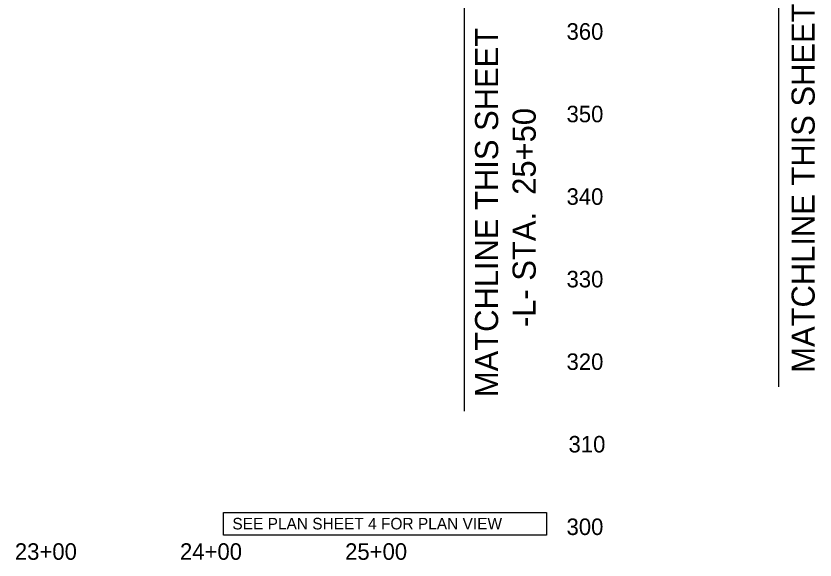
# Model space of a CAD drawing. Extents: x 2044664 to 2046614, y 755540 to 756566.
# Drawn here: x 2046130.2 to 2046614.2, y 756065.3 to 756394.8 of the extents above; entities that cross this region are included whole.
import ezdxf

# ---------------------------------------------------------------- set-up
doc = ezdxf.new("R2010")
doc.units = 0
for name, color, linetype in [('Exist Vertical Profile Horizontal Axis Label Major', 7, 'Continuous'), ('Exist Vertical Profile Vertical Axis Label', 7, 'Continuous'), ('Matchline', 7, 'Continuous'), ('Matchline Text', 7, 'Continuous'), ('Prop Grid Mask', 7, 'Continuous')]:
    doc.layers.add(name, color=color, linetype=linetype)

msp = doc.modelspace()

# ---------------------------------------------------------------- linework, layer by layer
at = {"layer": 'Matchline'}
for p, q in [((2046591.97, 756434.13), (2046591.97, 756170.18)), ((2046401.63, 756419.36), (2046401.63, 756155.41))]:
    msp.add_line(p, q, dxfattribs=at)
at = {"layer": 'Prop Grid Mask'}
msp.add_lwpolyline([(2046451.63, 756080.41), (2046255.85, 756080.42), (2046255.85, 756094.07), (2046451.64, 756094.07)], close=True, dxfattribs=at)

# ---------------------------------------------------------------- texts
at = {"layer": 'Exist Vertical Profile Horizontal Axis Label Major'}
for s, p in [('23+00', (2046129.57, 756065.41)), ('24+00', (2046229.57, 756065.41)), ('25+00', (2046329.57, 756065.41))]:
    msp.add_text(s, height=10, dxfattribs=at).set_placement(p)
at = {"layer": 'Exist Vertical Profile Vertical Axis Label'}
for s, p in [('360', (2046463.69, 756380.41)), ('350', (2046463.69, 756330.41)), ('340', (2046463.69, 756280.41)), ('330', (2046463.69, 756230.41)), ('320', (2046463.69, 756180.41)), ('310', (2046464.89, 756130.41)), ('300', (2046463.69, 756080.41))]:
    msp.add_text(s, height=10, dxfattribs=at).set_placement(p)
at = {"layer": 'Matchline Text'}
for s, p in [('MATCHLINE THIS SHEET', (2046613.97, 756178.71)), ('MATCHLINE THIS SHEET', (2046422.26, 756163.94)), ('-L- STA.  25+50', (2046445.01, 756206.39))]:
    msp.add_text(s, height=14, rotation=90, dxfattribs=at).set_placement(p)
at = {"layer": 'Prop Grid Mask'}
msp.add_text('SEE PLAN SHEET 4 FOR PLAN VIEW', height=7, rotation=359.9986, dxfattribs=at).set_placement((2046261.3, 756083.8))

doc.saveas('drawing.dxf')
